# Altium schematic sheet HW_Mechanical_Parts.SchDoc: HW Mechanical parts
size A4; Date: 19/04/2016; Author: N.P; CompanyName: STMicroelectronics; Organization: MCD/APPLIS/LMS; DocumentNumber: MB1260; SheetNumber: 13; SheetTotal: 13; Project: STM32F723e-DISCO
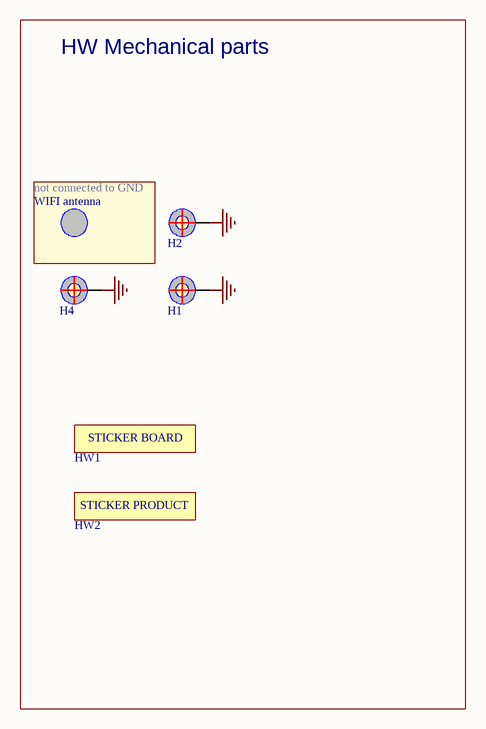
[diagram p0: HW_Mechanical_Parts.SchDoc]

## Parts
H1  POSITION HOLE C6D3R5  [HOLE_C6D3R5]  (value not drawn)  (no BOM)
H2  POSITION HOLE C6D3R5  [HOLE_C6D3R5]  (value not drawn)  (no BOM)
H4  POSITION HOLE C6D3R5  [HOLE_C6D3R5]  (value not drawn)  (no BOM)
HW1  STICKER_BOARD  (value not drawn)  (no BOM)
HW2  STICKER_PRODUCT  (value not drawn)  (no BOM)

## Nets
GND: H1.1 H2.1 H4.1

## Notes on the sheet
- HW Mechanical parts
- (near H2) not connected to GND
- WIFI antenna

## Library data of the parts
H1 H2 H4 = POSITION HOLE C6D3R5: Fitted: NO; Ordered by: Subcon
